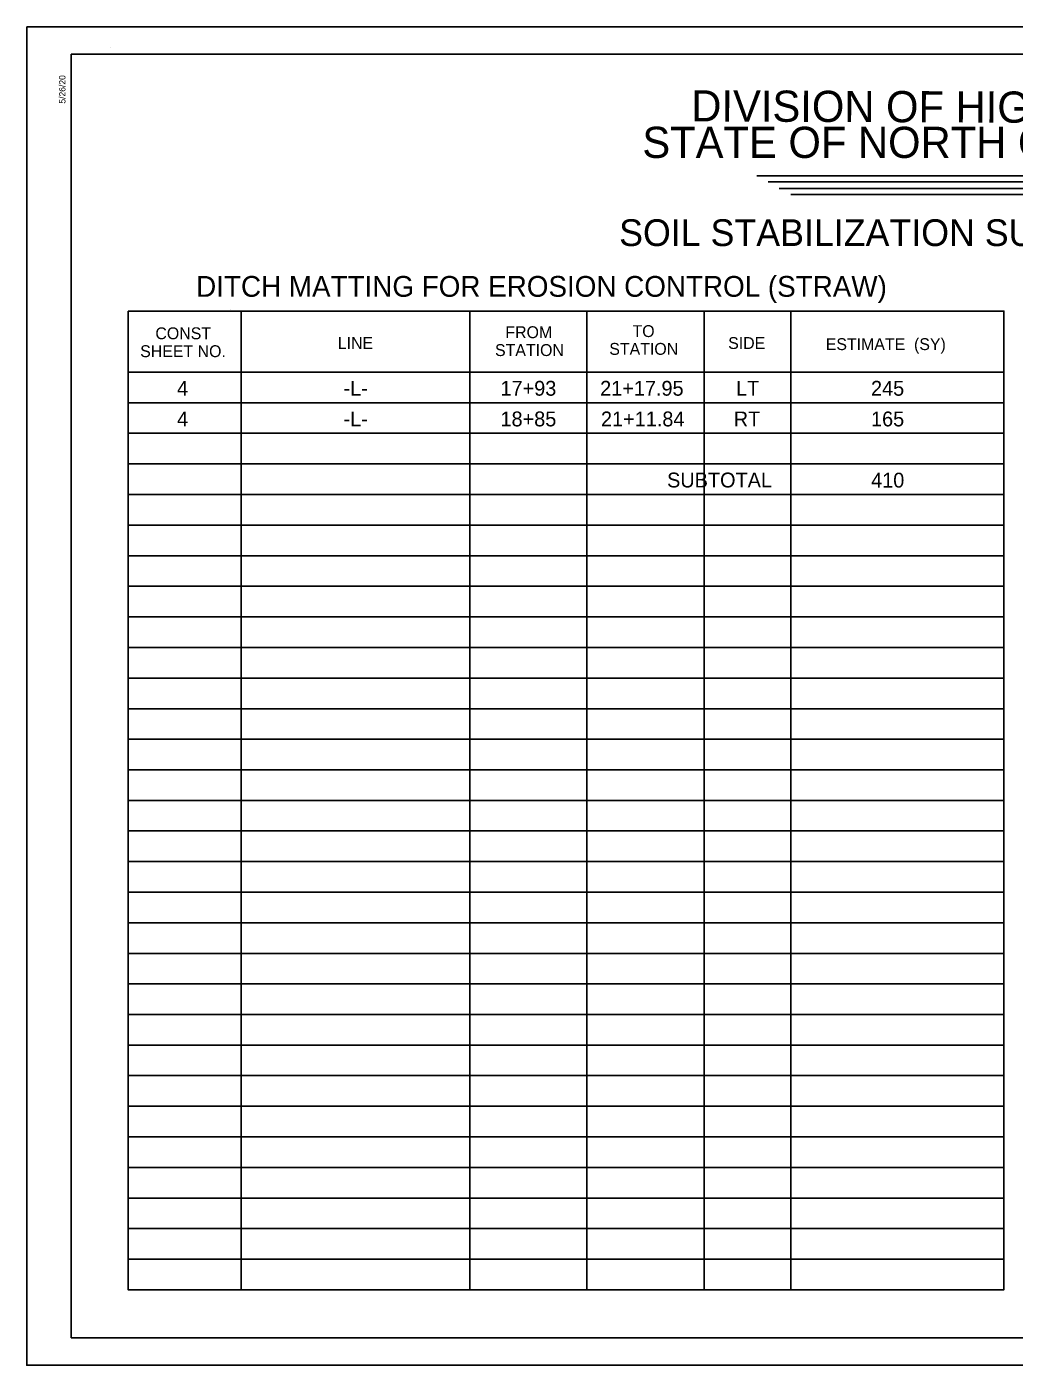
# Model space of a CAD drawing. Extents: x 1674550 to 1676250, y 1328139 to 1330492.
# Drawn here: x 1674550 to 1675361, y 1328139 to 1329239 of the extents above; entities that cross this region are included whole.
import ezdxf

# ---------------------------------------------------------------- set-up
doc = ezdxf.new("R2010")
doc.units = 0
for name, color, linetype in [('Blank Plan Sheet Both CELL', 7, 'Continuous'), ('Matting Summary Sheet CELL', 7, 'Continuous'), ('Sheet Data Field CELL', 7, 'Continuous'), ('Sheet Plan CELL', 7, 'Continuous'), ('Sheet Plot Border Outside CELL', 7, 'Continuous'), ('z - Construction', 7, 'Continuous')]:
    doc.layers.add(name, color=color, linetype=linetype)

msp = doc.modelspace()

# ---------------------------------------------------------------- linework, layer by layer
at = {"layer": 'Blank Plan Sheet Both CELL'}
msp.add_line((1674618.7, 1329221.9), (1674618.7, 1329221.9), dxfattribs=at)
at = {"layer": 'Matting Summary Sheet CELL'}
for p, q in [((1675149.8, 1329116.5), (1675570.9, 1329116.5)), ((1675159, 1329111.4), (1675561.3, 1329111.4)), ((1675168.2, 1329105.9), (1675551.7, 1329105.9)), ((1675177.8, 1329101), (1675542, 1329101)), ((1674717.2, 1329006.8), (1674717.2, 1329006.8)), ((1674725.9, 1329005.3), (1674725.9, 1328200.9)), ((1674913.8, 1329005.3), (1674913.8, 1328200.9)), ((1675010.1, 1329005.3), (1675010.1, 1328200.9)), ((1675106.4, 1329005.3), (1675106.4, 1328200.9)), ((1675177.8, 1329005.3), (1675177.8, 1328200.9)), ((1674633.1, 1328955), (1675352.8, 1328955)), ((1674633.1, 1328929.9), (1675352.8, 1328929.9)), ((1674633.1, 1328904.8), (1675352.8, 1328904.8)), ((1674633.1, 1328879.6), (1675352.8, 1328879.6)), ((1674633.1, 1328854.5), (1675352.8, 1328854.5)), ((1674633.1, 1328829.4), (1675352.8, 1328829.4)), ((1674633.1, 1328804.2), (1675352.8, 1328804.2)), ((1674633.1, 1328779.1), (1675352.8, 1328779.1)), ((1674633.1, 1328753.9), (1675352.8, 1328753.9)), ((1674633.1, 1328728.8), (1675352.8, 1328728.8)), ((1674633.1, 1328703.7), (1675352.8, 1328703.7)), ((1674633.1, 1328678.5), (1675352.8, 1328678.5)), ((1674633.1, 1328653.4), (1675352.8, 1328653.4)), ((1674633.1, 1328628.2), (1675352.8, 1328628.2)), ((1674633.1, 1328603.1), (1675352.8, 1328603.1)), ((1674633.1, 1328578), (1675352.8, 1328578)), ((1674633.1, 1328552.8), (1675352.8, 1328552.8)), ((1674633.1, 1328527.7), (1675352.8, 1328527.7)), ((1674633.1, 1328502.6), (1675352.8, 1328502.6)), ((1674633.1, 1328477.4), (1675352.8, 1328477.4)), ((1674633.1, 1328452.3), (1675352.8, 1328452.3)), ((1674633.1, 1328427.1), (1675352.8, 1328427.1)), ((1674633.1, 1328402), (1675352.8, 1328402)), ((1674633.1, 1328376.9), (1675352.8, 1328376.9)), ((1674633.1, 1328351.7), (1675352.8, 1328351.7)), ((1674633.1, 1328326.6), (1675352.8, 1328326.6)), ((1674633.1, 1328301.5), (1675352.8, 1328301.5)), ((1674633.1, 1328276.3), (1675352.8, 1328276.3)), ((1674633.1, 1328251.2), (1675352.8, 1328251.2)), ((1674633.1, 1328226), (1675352.8, 1328226))]:
    msp.add_line(p, q, dxfattribs=at)
msp.add_lwpolyline([(1674633.1, 1329005.3), (1675352.8, 1329005.3), (1675352.8, 1328200.9), (1674633.1, 1328200.9)], close=True, dxfattribs=at)
at = {"layer": 'Sheet Data Field CELL'}
msp.add_line((1674549.8, 1328138.9), (1674549.8, 1328138.9), dxfattribs=at)
at = {"layer": 'Sheet Plan CELL'}
for p, q in [((1674586.3, 1328161.4), (1674586.3, 1329216.4)), ((1676236.3, 1329216.4), (1674586.3, 1329216.4)), ((1674586.3, 1328161.4), (1676236.3, 1328161.4)), ((1674616.2, 1328161.4), (1674616.2, 1328161.4))]:
    msp.add_line(p, q, dxfattribs=at)
at = {"layer": 'Sheet Plot Border Outside CELL'}
msp.add_lwpolyline([(1674549.8, 1329238.9), (1676249.8, 1329238.9), (1676249.8, 1328138.9), (1674549.8, 1328138.9)], close=True, dxfattribs=at)
at = {"layer": 'z - Construction'}
for p, q in [((1676249.8, 1329238.9), (1674549.8, 1329238.9)), ((1674549.8, 1329238.9), (1674549.8, 1328138.9)), ((1674549.8, 1328138.9), (1676249.8, 1328138.9))]:
    msp.add_line(p, q, dxfattribs=at)

# ---------------------------------------------------------------- texts
at = {"layer": 'Matting Summary Sheet CELL'}
for s, height, rotation, p in [('  DIVISION OF HIGHWAYS', 25.64, 359.7699, (1675076.8, 1329161.2)), ('STATE OF NORTH CAROLINA', 25.64, 360, (1675055.7, 1329131.1)), ('SOIL STABILIZATION SUMMARY SHEET', 21.977, 360, (1675036.6, 1329058.7)), ('DITCH MATTING FOR EROSION CONTROL (STRAW)', 17.093, 360, (1674689, 1329017)), ('CONST', 9.77, 360, (1674655.5, 1328982.1)), ('LINE', 9.76, 360, (1674805.4, 1328974.2)), ('FROM ', 9.77, 360, (1674943.1, 1328983)), ('TO', 9.77, 360, (1675047.6, 1328983.9)), ('SIDE', 9.76, 360, (1675126.2, 1328974.1)), ('SHEET NO.', 9.77, 360, (1674643, 1328967.4)), ('STATION', 9.77, 360, (1674934.6, 1328968.3)), ('STATION', 9.77, 360, (1675028.5, 1328969.3)), ('ESTIMATE  (SY)', 9.763, 360, (1675206.4, 1328973.2)), ('4', 12.2, 360, (1674673.3, 1328935.7)), ('-L-', 12.21, 360, (1674810.1, 1328935.7)), ('17+93', 12.21, 360, (1674939.1, 1328935.7)), ('21+17.95', 12.21, 360, (1675021, 1328935.7)), ('LT', 12.21, 360, (1675132.7, 1328935.7)), ('245', 12.21, 360, (1675243.6, 1328935.7)), ('4', 12.2, 360, (1674673.3, 1328910.5)), ('-L-', 12.21, 360, (1674810.1, 1328910.5)), ('18+85', 12.21, 360, (1674939.1, 1328910.5)), ('21+11.84', 12.21, 360, (1675021.7, 1328910.5)), ('RT', 12.21, 360, (1675130.8, 1328910.5)), ('165', 12.21, 360, (1675243.6, 1328910.5)), ('SUBTOTAL', 12.21, 360, (1675076, 1328860.3)), ('410', 12.21, 360, (1675243.7, 1328860.2))]:
    msp.add_text(s, height=height, rotation=rotation, dxfattribs=at).set_placement(p)
at = {"layer": 'Sheet Plan CELL'}
msp.add_text('5/26/20', height=5.25, rotation=90, dxfattribs=at).set_placement((1674581.6, 1329175.7))

doc.saveas('drawing.dxf')
